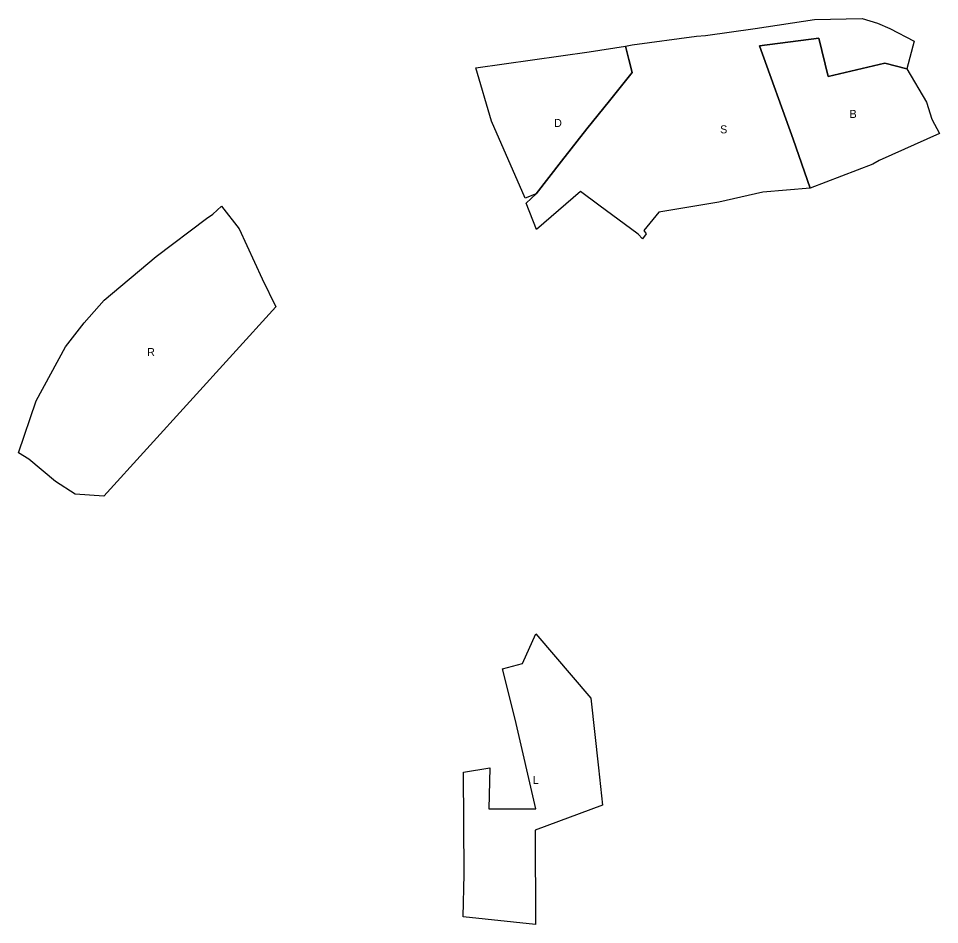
# Model space of a CAD drawing. Extents: x -476493 to -466317, y -1156890 to -1150260.
# Drawn here: x -472708 to -472132, y -1153949 to -1153383 of the extents above; entities that cross this region are included whole.
import ezdxf

# ---------------------------------------------------------------- set-up
doc = ezdxf.new("R2010")
doc.units = 0
for name, color, linetype in [('Vrstva 1', 7, 'Continuous'), ('Vrstva 2', 7, 'Continuous'), ('Vrstva 4', 7, 'Continuous'), ('Vrstva 6', 7, 'Continuous'), ('Vrstva 7', 7, 'Continuous')]:
    doc.layers.add(name, color=color, linetype=linetype)

msp = doc.modelspace()

# ---------------------------------------------------------------- linework, layer by layer
at = {"layer": 'Vrstva 1'}
msp.add_lwpolyline([(-472213.37, -1153489.24), (-472223.87, -1153458.49), (-472244.87, -1153400.18), (-472207.808, -1153395.395), (-472202.039, -1153419.449), (-472166.714, -1153411.19), (-472152.941, -1153414.66), (-472140.66, -1153435.43), (-472137.26, -1153446.15), (-472132.41, -1153455.08), (-472170.08, -1153471.85), (-472174.07, -1153474.24)], close=True, dxfattribs=at)
at = {"layer": 'Vrstva 2'}
msp.add_lwpolyline([(-472328.62, -1153400.52), (-472326.54, -1153408.77), (-472324.46, -1153417.02), (-472338.705, -1153434.54), (-472352.95, -1153452.06), (-472368.755, -1153472.365), (-472384.56, -1153492.67), (-472391.49, -1153495.4), (-472412.54, -1153447.37), (-472422.19, -1153413.95), (-472351.33, -1153404)], close=True, dxfattribs=at)
at = {"layer": 'Vrstva 4'}
msp.add_lwpolyline([(-472413.524, -1153851.445), (-472414.082, -1153877.111), (-472384.68, -1153877.18), (-472397.74, -1153821.02), (-472405.54, -1153789.58), (-472393.16, -1153786.23), (-472384.75, -1153767.67), (-472350.33, -1153807.9), (-472345.63, -1153851.47), (-472343.073, -1153874.923), (-472385.069, -1153890.501), (-472385.053, -1153949.491), (-472430.18, -1153944.56), (-472429.56, -1153918.07), (-472430.05, -1153854.19)], close=True, dxfattribs=at)
at = {"layer": 'Vrstva 6'}
msp.add_lwpolyline([(-472547.275, -1153563.415), (-472654.82, -1153681.79), (-472672.64, -1153680.55), (-472684.93, -1153672.54), (-472701.52, -1153658.55), (-472708.13, -1153654.58), (-472697.11, -1153622.2), (-472678.63, -1153588.29), (-472666.94, -1153573.37), (-472654.56, -1153559.3), (-472622.01, -1153532), (-472590.48, -1153508.1), (-472586.58, -1153505.55), (-472581.15, -1153500.47), (-472570.12, -1153514.71), (-472555.88, -1153545.9)], close=True, dxfattribs=at)
at = {"layer": 'Vrstva 7'}
msp.add_lwpolyline([(-472384.56, -1153492.67), (-472368.755, -1153472.365), (-472352.95, -1153452.06), (-472338.705, -1153434.54), (-472324.46, -1153417.02), (-472326.54, -1153408.77), (-472328.62, -1153400.52), (-472324.5, -1153399.71), (-472284.29, -1153394.23), (-472278.66, -1153393.76), (-472247.68, -1153389.5), (-472210.56, -1153383.87), (-472180.75, -1153383.12), (-472171.18, -1153386.12), (-472163.41, -1153389.46), (-472148.335, -1153397.39), (-472152.941, -1153414.66), (-472166.714, -1153411.19), (-472202.039, -1153419.449), (-472207.808, -1153395.395), (-472244.87, -1153400.18), (-472223.87, -1153458.49), (-472213.37, -1153489.24), (-472242.97, -1153491.77), (-472270.42, -1153498.01), (-472307.87, -1153504.19), (-472317.31, -1153515.76), (-472315.87, -1153517.72), (-472318.16, -1153520.78), (-472320.88, -1153517.97), (-472345.44, -1153499.74), (-472356.78, -1153491.26), (-472384.435, -1153514.96), (-472390.75, -1153498.62)], close=True, dxfattribs=at)

# ---------------------------------------------------------------- texts
at = {"layer": 'Vrstva 1'}
for s, p in [('B', (-472188.64, -1153445.318)), ('D', (-472373.325, -1153450.96)), ('S', (-472269.542, -1153454.95)), ('R', (-472627.702, -1153594.13)), ('L', (-472386.626, -1153861.58))]:
    msp.add_text(s, height=5, dxfattribs=at).set_placement(p)

doc.saveas('drawing.dxf')
